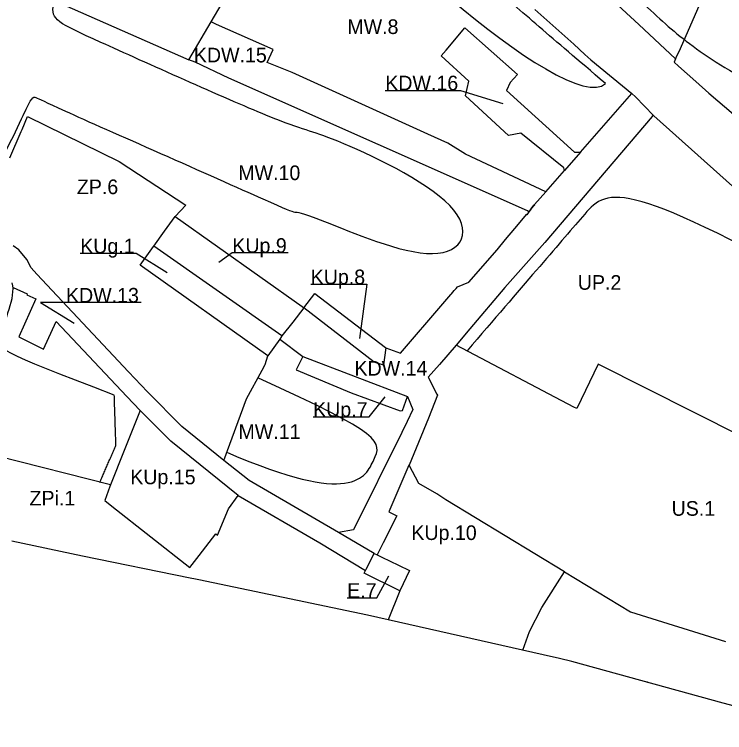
# Model space of a CAD drawing. Extents: x 7424788 to 7425732, y 5549810 to 5550591.
# Drawn here: x 7425041.7 to 7425235.6, y 5549835.2 to 5550031.4 of the extents above; entities that cross this region are included whole.
import ezdxf

# ---------------------------------------------------------------- set-up
doc = ezdxf.new("R2010")
doc.units = 0
for name, color, linetype in [('WIL_granica obszaru objętego planem', 7, 'Continuous'), ('WIL_linia rozgraniczające tereny o różnym przeznaczeniu lub różnych zasadach zagospodarowania', 7, 'Continuous'), ('WIL_linia rozgraniczające tereny o różnym przeznaczeniu lub różnych zasadach zagospodarowania_OPISY', 7, 'Continuous'), ('WIL_nieprzekraczalne linie zabudowy', 7, 'Continuous')]:
    doc.layers.add(name, color=color, linetype=linetype)

msp = doc.modelspace()

# ---------------------------------------------------------------- linework, layer by layer
at = {"layer": 'WIL_granica obszaru objętego planem'}
for p, q in [((7425060.24, 5549883.4), (7425040.93, 5549887.52)), ((7425089.69, 5549877.44), (7425060.24, 5549883.4)), ((7425091.14, 5549877.15), (7425089.69, 5549877.44)), ((7425092, 5549876.97), (7425091.14, 5549877.15)), ((7425138.07, 5549867.3), (7425092, 5549876.97)), ((7425180.44, 5549857.76), (7425138.07, 5549867.3)), ((7425193.92, 5549854.62), (7425190.49, 5549855.44)), ((7425235.24, 5549843.32), (7425193.92, 5549854.62))]:
    msp.add_line(p, q, dxfattribs=at)
for points in [[(7425190.49, 5549855.44), (7425186.05, 5549856.5), (7425180.44, 5549857.76)], [(7425270.8, 5549835.23), (7425250.01, 5549839.34), (7425235.24, 5549843.32)]]:
    msp.add_lwpolyline(points, dxfattribs=at)
msp.add_open_spline([(7425214.64, 5549848.95), (7425214.47, 5549849)], degree=1, dxfattribs=at)
at = {"layer": 'WIL_linia rozgraniczające tereny o różnym przeznaczeniu lub różnych zasadach zagospodarowania'}
for p, q in [((7425212.17, 5550028.66), (7425194.11, 5550045.49)), ((7425041.96, 5550039.92), (7425089.34, 5550019)), ((7425095.42, 5550029.4), (7425098.4, 5550034.5)), ((7425183.81, 5550032.81), (7425194.4, 5550023.28)), ((7425228.57, 5550033.67), (7425223.07, 5550021.22)), ((7425089.34, 5550019), (7425095.42, 5550029.4)), ((7425096.83, 5550028.69), (7425095.42, 5550029.4)), ((7425112.32, 5550021.87), (7425096.83, 5550028.69)), ((7425222.22, 5550019.29), (7425212.17, 5550028.66)), ((7425159.54, 5550021.69), (7425164.68, 5550027.76)), ((7425164.68, 5550027.76), (7425179.1, 5550015.05)), ((7425194.4, 5550023.28), (7425197.46, 5550020.51)), ((7425110.73, 5550018.28), (7425112.32, 5550021.87)), ((7425158.17, 5550020.08), (7425159.54, 5550021.69)), ((7425223.07, 5550021.22), (7425222.52, 5550019.98)), ((7425091.05, 5550018.36), (7425089.34, 5550019)), ((7425165.78, 5550013.15), (7425158.17, 5550020.08)), ((7425197.46, 5550020.51), (7425199.08, 5550019.03)), ((7425199.08, 5550019.03), (7425210.27, 5550009.78)), ((7425222.22, 5550019.29), (7425221.82, 5550018.38)), ((7425222.52, 5550019.98), (7425222.22, 5550019.29)), ((7425100.24, 5550014.02), (7425091.05, 5550018.36)), ((7425117.48, 5550015.54), (7425110.73, 5550018.28)), ((7425221.82, 5550018.38), (7425223, 5550017.31)), ((7425223, 5550017.31), (7425227.76, 5550013.1)), ((7425128.5, 5550010.51), (7425117.48, 5550015.54)), ((7425179.1, 5550015.05), (7425177.09, 5550012.8)), ((7425181.83, 5549977.74), (7425100.24, 5550014.02)), ((7425164.89, 5550009.22), (7425165.78, 5550013.15)), ((7425177.09, 5550012.8), (7425176.08, 5550010.67)), ((7425227.76, 5550013.1), (7425231.35, 5550009.93)), ((7425154.55, 5549998.74), (7425128.5, 5550010.51)), ((7425176.64, 5549998.36), (7425164.89, 5550009.22)), ((7425176.08, 5550010.67), (7425194.66, 5549993.77)), ((7425196.22, 5549993.77), (7425210.27, 5550009.78)), ((7425210.27, 5550009.78), (7425211.26, 5550008.96)), ((7425211.26, 5550008.96), (7425216.23, 5550003.85)), ((7425231.35, 5550009.93), (7425238.05, 5550004.15)), ((7425043.8, 5549999.96), (7425045.27, 5550003.58)), ((7425045.27, 5550003.58), (7425070.25, 5549991.28)), ((7425215.86, 5550003.56), (7425186.5, 5549969.15)), ((7425216.23, 5550003.85), (7425215.86, 5550003.56)), ((7425216.23, 5550003.85), (7425216.3, 5550003.77)), ((7425216.3, 5550003.77), (7425241.29, 5549981.33)), ((7425040.46, 5549992.28), (7425043.54, 5549999.42)), ((7425043.54, 5549999.42), (7425043.8, 5549999.96)), ((7425180, 5549999.03), (7425176.64, 5549998.36)), ((7425191.75, 5549989.52), (7425180, 5549999.03)), ((7425160.05, 5549996.26), (7425154.55, 5549998.74)), ((7425164.86, 5549993.27), (7425160.05, 5549996.26)), ((7425186.76, 5549982.99), (7425164.86, 5549993.27)), ((7425196.22, 5549993.77), (7425191.87, 5549988.81)), ((7425194.66, 5549993.77), (7425196.22, 5549993.77)), ((7425070.25, 5549991.28), (7425088.44, 5549979.36)), ((7425191.87, 5549988.81), (7425191.75, 5549989.52)), ((7425186.76, 5549982.99), (7425191.87, 5549988.81)), ((7425183.69, 5549979.49), (7425186.76, 5549982.99)), ((7425088.44, 5549979.36), (7425085.53, 5549976.27)), ((7425183.76, 5549979.44), (7425182.82, 5549978.31)), ((7425183.76, 5549979.44), (7425182.82, 5549978.31)), ((7425183.53, 5549979.31), (7425183.69, 5549979.49)), ((7425183.53, 5549979.31), (7425183.69, 5549979.49)), ((7425183.69, 5549979.49), (7425183.76, 5549979.44)), ((7425183.69, 5549979.49), (7425183.76, 5549979.44)), ((7425181.68, 5549976.72), (7425182.82, 5549978.31)), ((7425182.13, 5549977.49), (7425181.83, 5549977.74)), ((7425182.82, 5549978.31), (7425182.13, 5549977.49)), ((7425182.82, 5549978.31), (7425183.53, 5549979.31)), ((7425182.82, 5549978.31), (7425183.53, 5549979.31)), ((7425082.64, 5549972.2), (7425085.53, 5549976.27)), ((7425085.53, 5549976.27), (7425120.26, 5549951.64)), ((7425178.32, 5549972.97), (7425181.62, 5549976.87)), ((7425181.62, 5549976.87), (7425181.64, 5549976.89)), ((7425181.64, 5549976.89), (7425181.68, 5549976.72)), ((7425079.74, 5549968.12), (7425082.64, 5549972.2)), ((7425175.77, 5549969.93), (7425178.32, 5549972.97)), ((7425173.49, 5549967.14), (7425175.77, 5549969.93)), ((7425042.87, 5549967.11), (7425041.35, 5549968.17)), ((7425076.04, 5549962.91), (7425079.68, 5549968.04)), ((7425079.68, 5549968.04), (7425079.74, 5549968.12)), ((7425114.74, 5549943.6), (7425079.74, 5549968.12)), ((7425186.5, 5549969.15), (7425175.58, 5549956.84)), ((7425045.03, 5549964.44), (7425042.87, 5549967.11)), ((7425165.72, 5549958.32), (7425173.49, 5549967.14)), ((7425046.22, 5549962.17), (7425045.03, 5549964.44)), ((7425047.83, 5549960.5), (7425046.22, 5549962.17)), ((7425110.91, 5549938.18), (7425076.04, 5549962.91)), ((7425072.84, 5549933.8), (7425047.83, 5549960.5)), ((7425162.68, 5549957.04), (7425165.72, 5549958.32)), ((7425041.35, 5549956.83), (7425045.15, 5549955.11)), ((7425160.99, 5549955.08), (7425161.8, 5549956.02)), ((7425161.8, 5549956.02), (7425162.27, 5549956.57)), ((7425162.27, 5549956.57), (7425162.68, 5549957.04)), ((7425175.58, 5549956.84), (7425166.02, 5549945.5)), ((7425045.15, 5549955.11), (7425045.02, 5549954.86)), ((7425045.02, 5549954.86), (7425047.54, 5549953.73)), ((7425120.73, 5549951.27), (7425123.75, 5549955.23)), ((7425123.75, 5549955.23), (7425143.02, 5549940.41)), ((7425158.7, 5549952.36), (7425160.84, 5549954.9)), ((7425160.84, 5549954.9), (7425160.99, 5549955.08)), ((7425047.54, 5549953.73), (7425042.85, 5549943.33)), ((7425147.12, 5549938.92), (7425158.7, 5549952.36)), ((7425120.73, 5549951.27), (7425117.67, 5549947.35)), ((7425120.26, 5549951.64), (7425120.73, 5549951.27)), ((7425139.94, 5549936.43), (7425120.73, 5549951.27)), ((7425049.64, 5549939.97), (7425053.04, 5549947.56)), ((7425053.04, 5549947.56), (7425072.34, 5549927.04)), ((7425117.67, 5549947.35), (7425114.74, 5549943.6)), ((7425166.02, 5549945.5), (7425162.31, 5549941.12)), ((7425042.85, 5549943.33), (7425049.64, 5549939.97)), ((7425114.13, 5549942.74), (7425110.91, 5549938.18)), ((7425114.64, 5549943.47), (7425114.13, 5549942.74)), ((7425114.13, 5549942.74), (7425120.44, 5549937.99)), ((7425114.71, 5549943.56), (7425114.64, 5549943.47)), ((7425114.74, 5549943.6), (7425114.71, 5549943.56)), ((7425143.14, 5549940.37), (7425142.47, 5549935.67)), ((7425143.02, 5549940.41), (7425143.14, 5549940.37)), ((7425143.14, 5549940.37), (7425147.12, 5549938.92)), ((7425162.31, 5549941.12), (7425157.76, 5549935.75)), ((7425194.46, 5549924.15), (7425162.31, 5549941.12)), ((7425110.19, 5549935.84), (7425110.91, 5549938.18)), ((7425120.44, 5549937.99), (7425118.62, 5549934.3)), ((7425120.44, 5549937.99), (7425149.06, 5549927.05)), ((7425142.18, 5549935.7), (7425139.94, 5549936.43)), ((7425105.08, 5549926.42), (7425109.31, 5549934.22)), ((7425109.31, 5549934.22), (7425110.06, 5549935.6)), ((7425110.06, 5549935.6), (7425110.19, 5549935.84)), ((7425118.62, 5549934.3), (7425133.6, 5549928.07)), ((7425142.31, 5549935.69), (7425142.18, 5549935.7)), ((7425142.47, 5549935.67), (7425142.31, 5549935.69)), ((7425157.76, 5549935.75), (7425154.7, 5549932.3)), ((7425201.1, 5549935.93), (7425195.23, 5549923.82)), ((7425268.92, 5549901.61), (7425201.1, 5549935.93)), ((7425077.98, 5549928.31), (7425072.84, 5549933.8)), ((7425154.7, 5549932.3), (7425157.06, 5549927.7)), ((7425072.34, 5549927.04), (7425075.97, 5549923.22)), ((7425087.38, 5549918.84), (7425077.98, 5549928.31)), ((7425098.89, 5549909.61), (7425105.08, 5549926.42)), ((7425133.6, 5549928.07), (7425147.05, 5549923.15)), ((7425147.61, 5549923.21), (7425149.06, 5549927.05)), ((7425149.06, 5549927.05), (7425150.51, 5549923.48)), ((7425157.2, 5549927.41), (7425154.76, 5549921.18)), ((7425157.06, 5549927.7), (7425157.2, 5549927.41)), ((7425075.97, 5549923.22), (7425071.64, 5549912.3)), ((7425084.36, 5549914.88), (7425075.97, 5549923.22)), ((7425147.05, 5549923.15), (7425147.61, 5549923.21)), ((7425150.51, 5549923.48), (7425148.9, 5549920.19)), ((7425195.23, 5549923.82), (7425194.46, 5549924.15)), ((7425154.76, 5549921.18), (7425151.98, 5549914.45)), ((7425098.89, 5549909.61), (7425087.38, 5549918.84)), ((7425148.9, 5549920.19), (7425147.46, 5549917.23)), ((7425147.46, 5549917.23), (7425134.24, 5549890.59)), ((7425102.79, 5549900.03), (7425084.36, 5549914.88)), ((7425067.94, 5549902.95), (7425025.04, 5549913.83)), ((7425151.98, 5549914.45), (7425149.45, 5549908.31)), ((7425071.64, 5549912.3), (7425067.94, 5549902.95)), ((7425105.74, 5549904.11), (7425098.89, 5549909.61)), ((7425149.42, 5549908.29), (7425143.89, 5549895.52)), ((7425149.45, 5549908.37), (7425149.42, 5549908.29)), ((7425149.45, 5549908.31), (7425149.45, 5549908.37)), ((7425152.09, 5549903.26), (7425149.45, 5549908.31)), ((7425067.94, 5549902.95), (7425067.74, 5549902.45)), ((7425130.15, 5549889.87), (7425105.74, 5549904.11)), ((7425157.01, 5549900.42), (7425152.09, 5549903.26)), ((7425067.74, 5549902.45), (7425066.35, 5549898.65)), ((7425100.12, 5549896.35), (7425102.79, 5549900.03)), ((7425102.79, 5549900.03), (7425125.1, 5549887.06)), ((7425159.51, 5549898.86), (7425157.01, 5549900.42)), ((7425066.35, 5549898.65), (7425068.26, 5549897.08)), ((7425068.26, 5549897.08), (7425089.6, 5549880.34)), ((7425191.9, 5549879.14), (7425159.51, 5549898.86)), ((7425097.12, 5549889.2), (7425100.12, 5549896.35)), ((7425143.89, 5549895.52), (7425146.11, 5549894.47)), ((7425146.11, 5549894.47), (7425142.39, 5549887.07)), ((7425092.11, 5549883.61), (7425096.69, 5549889.53)), ((7425096.69, 5549889.53), (7425097.12, 5549889.2)), ((7425134.24, 5549890.59), (7425130.15, 5549889.87)), ((7425139.89, 5549884.19), (7425130.15, 5549889.87)), ((7425060.24, 5549883.4), (7425040.93, 5549887.52)), ((7425125.1, 5549887.06), (7425137.5, 5549879.48)), ((7425142.39, 5549887.07), (7425140.75, 5549883.76)), ((7425089.69, 5549877.44), (7425060.24, 5549883.4)), ((7425089.6, 5549880.34), (7425092.11, 5549883.61)), ((7425137.72, 5549879.91), (7425139.89, 5549884.19)), ((7425139.89, 5549884.19), (7425140.75, 5549883.76)), ((7425140.75, 5549883.76), (7425142.01, 5549883.14)), ((7425142.01, 5549883.14), (7425146.57, 5549881)), ((7425137.14, 5549878.76), (7425137.5, 5549879.48)), ((7425137.5, 5549879.48), (7425137.72, 5549879.91)), ((7425146.57, 5549881), (7425149.57, 5549879.56)), ((7425149.57, 5549879.56), (7425146.92, 5549873.94)), ((7425091.14, 5549877.15), (7425089.69, 5549877.44)), ((7425146.92, 5549873.94), (7425137.14, 5549878.76)), ((7425185.71, 5549869.45), (7425191.9, 5549879.14)), ((7425191.9, 5549879.14), (7425209.88, 5549868.2)), ((7425092, 5549876.97), (7425091.14, 5549877.15)), ((7425138.07, 5549867.3), (7425092, 5549876.97)), ((7425146.92, 5549873.94), (7425143.78, 5549866.02)), ((7425182.31, 5549862.83), (7425185.7, 5549869.43)), ((7425185.7, 5549869.43), (7425185.71, 5549869.45)), ((7425209.88, 5549868.2), (7425235.83, 5549860.15)), ((7425180.44, 5549857.76), (7425138.07, 5549867.3)), ((7425180.51, 5549857.74), (7425182.31, 5549862.82)), ((7425182.31, 5549862.82), (7425182.31, 5549862.83)), ((7425193.92, 5549854.62), (7425190.49, 5549855.44)), ((7425235.24, 5549843.32), (7425193.92, 5549854.62))]:
    msp.add_line(p, q, dxfattribs=at)
for points in [[(7425190.49, 5549855.44), (7425186.05, 5549856.5), (7425180.44, 5549857.76)], [(7425270.8, 5549835.23), (7425250.01, 5549839.34), (7425235.24, 5549843.32)]]:
    msp.add_lwpolyline(points, dxfattribs=at)
at = {"layer": 'WIL_linia rozgraniczające tereny o różnym przeznaczeniu lub różnych zasadach zagospodarowania_OPISY'}
for points in [[(7425142.94, 5550010.69), (7425163.49, 5550010.69), (7425175.01, 5550007.13)], [(7425059.64, 5549966.17), (7425074.92, 5549966.17), (7425083.41, 5549960.97)], [(7425116.45, 5549966.3), (7425101.17, 5549966.3), (7425097.5, 5549963.62)], [(7425122.58, 5549957.72), (7425137.87, 5549957.72), (7425135.9, 5549942.94)], [(7425076.3, 5549952.71), (7425048.83, 5549952.71), (7425058, 5549947.1)], [(7425123.23, 5549921.5), (7425138.51, 5549921.5), (7425142.96, 5549926.98)], [(7425132.54, 5549872.06), (7425140.68, 5549872.06), (7425143.89, 5549878.07)]]:
    msp.add_lwpolyline(points, dxfattribs=at)
at = {"layer": 'WIL_nieprzekraczalne linie zabudowy'}
for points, degree in [([(7425084, 5550116.97), (7425064.39, 5550084.82), (7425059.12, 5550086.67), (7425051.28, 5550078.98), (7425041.03, 5550054.98), (7425041.88, 5550039.52), (7425016.38, 5550001.91), (7425010.97, 5549988.95), (7425023.53, 5549982.92), (7425032.48, 5549978.98), (7425046.3, 5550008.75), (7425046.87, 5550009.18), (7425051.43, 5550006.76), (7425080.91, 5549993.79), (7425114.24, 5549978.91), (7425118.94, 5549976.91), (7425119.45, 5549978.1), (7425161.39, 5549959.96), (7425169.94, 5549978.62), (7425122.22, 5550000.85), (7425121.22, 5549998.57), (7425055.13, 5550028.34), (7425049.86, 5550030.83), (7425059.26, 5550053.19), (7425084.9, 5550042.08), (7425096.96, 5550036.41), (7425124.07, 5550078.83)], 3), ([(7425132.48, 5550073.42), (7425123.93, 5550063.74), (7425193.39, 5550002.62), (7425203.07, 5550012.58)], 3), ([(7425203.07, 5550012.58), (7425195.36, 5550019.12), (7425184.47, 5550028.49), (7425171.34, 5550039.79), (7425160.93, 5550049.06), (7425152, 5550056.61), (7425139.95, 5550067.04), (7425135.9, 5550070.57), (7425132.48, 5550073.42)], 3), ([(7425197.48, 5550049.33), (7425201.22, 5550045.72), (7425214.43, 5550033.52), (7425224.47, 5550023.95), (7425243.95, 5550011.41), (7425259.92, 5550004.53), (7425266.6, 5550002.11)], 3), ([(7425264.48, 5549955.27), (7425206.42, 5549987.57), (7425200.28, 5549980.12), (7425180.2, 5549956.9), (7425165.28, 5549939.53)], 3), ([(7425068.94, 5549927.44), (7425037.04, 5549939.67), (7425035.61, 5549940.52), (7425042.17, 5549954.34), (7425041.09, 5549958.06)], 3), ([(7425099.86, 5549911.75), (7425134.04, 5549896.93), (7425141.17, 5549912.89), (7425142.88, 5549916.45), (7425108.12, 5549932.12)], 3), ([(7425069.39, 5549913.68), (7425068.94, 5549927.44)], 1), ([(7425064.95, 5549903.52), (7425069.39, 5549913.68)], 1)]:
    msp.add_open_spline(points, degree=degree, dxfattribs=at)

# ---------------------------------------------------------------- texts
at = {"layer": 'WIL_linia rozgraniczające tereny o różnym przeznaczeniu lub różnych zasadach zagospodarowania_OPISY'}
for s, p in [('MW.8', (7425132.58, 5550026.08)), ('KDW.15', (7425090.67, 5550018.32)), ('KDW.16', (7425142.94, 5550010.69)), ('MW.10', (7425102.8, 5549986.17)), ('ZP.6', (7425058.72, 5549982.33)), ('KUg.1', (7425059.64, 5549966.17)), ('KUp.9', (7425101.17, 5549966.3)), ('KUp.8', (7425122.58, 5549957.72)), ('UP.2', (7425195.52, 5549956.21)), ('KDW.13', (7425055.75, 5549952.71)), ('KDW.14', (7425134.53, 5549932.76)), ('KUp.7', (7425123.23, 5549921.5)), ('MW.11', (7425102.85, 5549915.45)), ('KUp.15', (7425073.3, 5549903.08)), ('ZPi.1', (7425045.79, 5549897.28)), ('US.1', (7425221.14, 5549894.47)), ('KUp.10', (7425150.07, 5549887.85)), ('E.7', (7425132.54, 5549872.06))]:
    msp.add_text(s, height=4, dxfattribs=at).set_placement(p)

doc.saveas('drawing.dxf')
